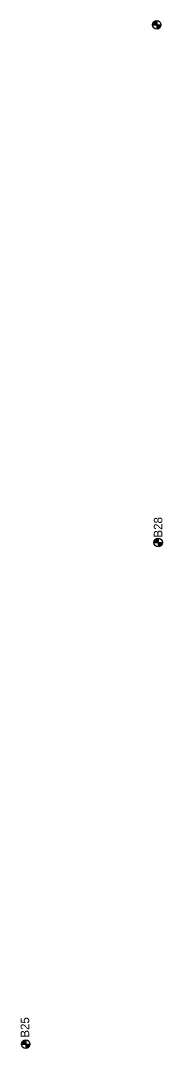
# Model space of a CAD drawing. Extents: x 345549 to 379569, y 127949 to 230467.
# Drawn here: x 361707 to 361873, y 142732 to 143930 of the extents above; entities that cross this region are included whole.
import ezdxf

# ---------------------------------------------------------------- set-up
doc = ezdxf.new("R2010")
doc.units = 0
doc.layers.add('E_SOIL_BORE2 [KAPUR_CADDS_LEVELS]', color=7, linetype='Continuous')
doc.layers.add('P_MARK', color=7, linetype='Continuous')

msp = doc.modelspace()

# ---------------------------------------------------------------- linework, layer by layer
at = {"layer": 'P_MARK'}
for p, q in [((361861.3, 143924.9), (361871.3, 143924.9)), ((361866.3, 143929.9), (361866.3, 143919.9)), ((361868, 143326.3), (361868, 143316.3)), ((361863, 143321.3), (361873, 143321.3)), ((361713.4, 142741.6), (361713.4, 142731.6)), ((361708.4, 142736.6), (361718.4, 142736.6))]:
    msp.add_line(p, q, dxfattribs=at)
for centre in [(361866.3, 143924.9), (361868, 143321.3), (361713.4, 142736.6)]:
    msp.add_circle(centre, 5, dxfattribs=at)
for centre, radius, start, end in [((361866.3, 143924.9), 4.5, 89.9869, 179.9869), ((361866.3, 143924.9), 4, 89.9869, 179.9869), ((361866.3, 143924.9), 3.5, 89.9869, 179.9869), ((361866.3, 143924.9), 3, 89.9869, 179.9869), ((361866.3, 143924.9), 2.5, 89.9869, 179.9869), ((361866.3, 143924.9), 2, 89.9869, 179.9869), ((361866.3, 143924.9), 1.5, 89.9869, 179.9869), ((361866.3, 143924.9), 1, 89.9869, 179.9869), ((361866.3, 143924.9), 0.5, 89.9869, 179.9869), ((361866.3, 143924.9), 4.5, 269.9869, 359.9869), ((361866.3, 143924.9), 4, 269.9869, 359.9869), ((361866.3, 143924.9), 3.5, 269.9869, 359.9869), ((361866.3, 143924.9), 3, 269.9869, 359.9869), ((361866.3, 143924.9), 2.5, 269.9869, 359.9869), ((361866.3, 143924.9), 2, 269.9869, 359.9869), ((361866.3, 143924.9), 1.5, 269.9869, 359.9869), ((361866.3, 143924.9), 1, 269.9869, 359.9869), ((361866.3, 143924.9), 0.5, 269.9869, 359.9869), ((361868, 143321.3), 4.5, 89.9869, 179.9869), ((361868, 143321.3), 4, 89.9869, 179.9869), ((361868, 143321.3), 3.5, 89.9869, 179.9869), ((361868, 143321.3), 3, 89.9869, 179.9869), ((361868, 143321.3), 2.5, 89.9869, 179.9869), ((361868, 143321.3), 2, 89.9869, 179.9869), ((361868, 143321.3), 1.5, 89.9869, 179.9869), ((361868, 143321.3), 1, 89.9869, 179.9869), ((361868, 143321.3), 0.5, 89.9869, 179.9869), ((361868, 143321.3), 4.5, 269.9869, 359.9869), ((361868, 143321.3), 4, 269.9869, 359.9869), ((361868, 143321.3), 3.5, 269.9869, 359.9869), ((361868, 143321.3), 3, 269.9869, 359.9869), ((361868, 143321.3), 2.5, 269.9869, 359.9869), ((361868, 143321.3), 2, 269.9869, 359.9869), ((361868, 143321.3), 1.5, 269.9869, 359.9869), ((361868, 143321.3), 1, 269.9869, 359.9869), ((361868, 143321.3), 0.5, 269.9869, 359.9869), ((361713.4, 142736.6), 4.5, 89.9869, 179.9869), ((361713.4, 142736.6), 4, 89.9869, 179.9869), ((361713.4, 142736.6), 3.5, 89.9869, 179.9869), ((361713.4, 142736.6), 3, 89.9869, 179.9869), ((361713.4, 142736.6), 2.5, 89.9869, 179.9869), ((361713.4, 142736.6), 2, 89.9869, 179.9869), ((361713.4, 142736.6), 1.5, 89.9869, 179.9869), ((361713.4, 142736.6), 1, 89.9869, 179.9869), ((361713.4, 142736.6), 0.5, 89.9869, 179.9869), ((361713.4, 142736.6), 4.5, 269.9869, 359.9869), ((361713.4, 142736.6), 4, 269.9869, 359.9869), ((361713.4, 142736.6), 3.5, 269.9869, 359.9869), ((361713.4, 142736.6), 3, 269.9869, 359.9869), ((361713.4, 142736.6), 2.5, 269.9869, 359.9869), ((361713.4, 142736.6), 2, 269.9869, 359.9869), ((361713.4, 142736.6), 1.5, 269.9869, 359.9869), ((361713.4, 142736.6), 1, 269.9869, 359.9869), ((361713.4, 142736.6), 0.5, 269.9869, 359.9869)]:
    msp.add_arc(centre, radius, start, end, dxfattribs=at)

# ---------------------------------------------------------------- texts
at = {"layer": 'E_SOIL_BORE2 [KAPUR_CADDS_LEVELS]'}
for s, p in [('B28', (361872.9, 143327.2)), ('B25', (361717.5, 142744.2))]:
    msp.add_text(s, height=10, rotation=89.9869, dxfattribs=at).set_placement(p)

doc.saveas('drawing.dxf')
